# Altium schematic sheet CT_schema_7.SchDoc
size 226 x 144 mm
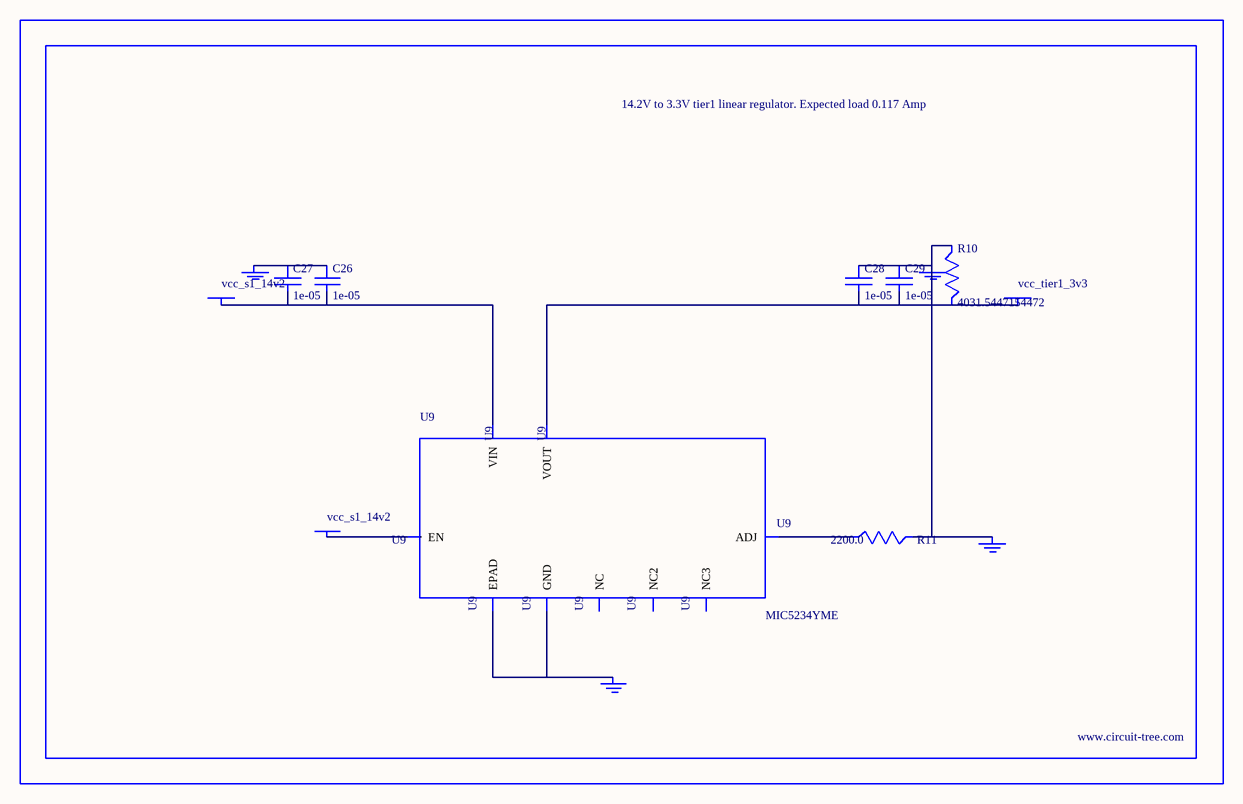
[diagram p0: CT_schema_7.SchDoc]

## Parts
BORDER6  (no value)
C26  1e-05  [C1210]
C27  1e-05  [C1210]
C28  1e-05  [C1210]
C29  1e-05  [C1210]
GND_INSTANCE_6_0  (no value)
GND_INSTANCE_6_1  (no value)
GND_INSTANCE_6_2  (no value)
GND_INSTANCE_6_3  (no value)
POWER_INSTANCE_6_0  vcc_tier1_3v3
POWER_INSTANCE_6_1  vcc_s1_14v2
POWER_INSTANCE_6_2  vcc_s1_14v2
R10  4031.5447154472  [R0603]
R11  2200.0  [R0603]
U9  MIC5234YME  [SOIC-8_EP]

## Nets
NetC26_1: C26.1 C27.1 GND_INSTANCE_6_3.0(GND)
NetC26_2: C26.2 C27.2 POWER_INSTANCE_6_2.0(PWR) U9.8(VIN)
NetC28_1: C28.1 C29.1 GND_INSTANCE_6_0.0(GND) GND_INSTANCE_6_1.0(GND) R10.1 R11.2
NetC28_2: C28.2 C29.2 POWER_INSTANCE_6_0.0(PWR) R10.2 U9.1(VOUT)
NetGND_INSTANCE_6_2_0: GND_INSTANCE_6_2.0(GND) U9.7(GND) U9.EPAD
NetPOWER_INSTANCE_6_1_0: POWER_INSTANCE_6_1.0(PWR) U9.5(EN)
NetR11_1: R11.1 U9.4(ADJ)

Not connected (* = marked no-connect by the designer): U9 2(NC) 3(NC2) 6(NC3)

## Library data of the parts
BORDER6 = BORDER_PAGE6
C26-C29 = C1210C106K5PACTU
GND_INSTANCE_6_0-GND_INSTANCE_6_3 = GND
POWER_INSTANCE_6_0-POWER_INSTANCE_6_2 = PWR
R10 = R10
R11 = RC0603JR-072K2L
